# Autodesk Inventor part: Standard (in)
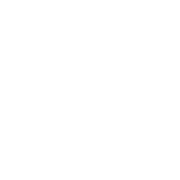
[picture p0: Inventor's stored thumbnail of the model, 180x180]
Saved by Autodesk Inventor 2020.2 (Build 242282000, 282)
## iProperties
Shininess: 64.0
Length Units: 11272
Angle Units: 11279
Time Units: 11290
Mass Units: 11286
Length Display Precision: 3
Angle Display Precision: 2
Compacted: True
Manager: www.cadconsulting.pl
Company: Fabian Stasiak CAD Consulting
Part Number: Standard (in)
Document SubType Name: Modeling
Created: 2002-08
Designer: F.Stasiak
Density: 1 g/cm^3
Material: Generic
Appearance: Default
Density: 0.0
Volumn: 0.0
Area: 0.0
PropertySet Name: Model Information
Control State: 0
Master: False
Checked Out: False
Author: F.Stasiak
Subject: Zbiór ćwiczeń. Autodesk Inventor 2020. Kurs podstawowy
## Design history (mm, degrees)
